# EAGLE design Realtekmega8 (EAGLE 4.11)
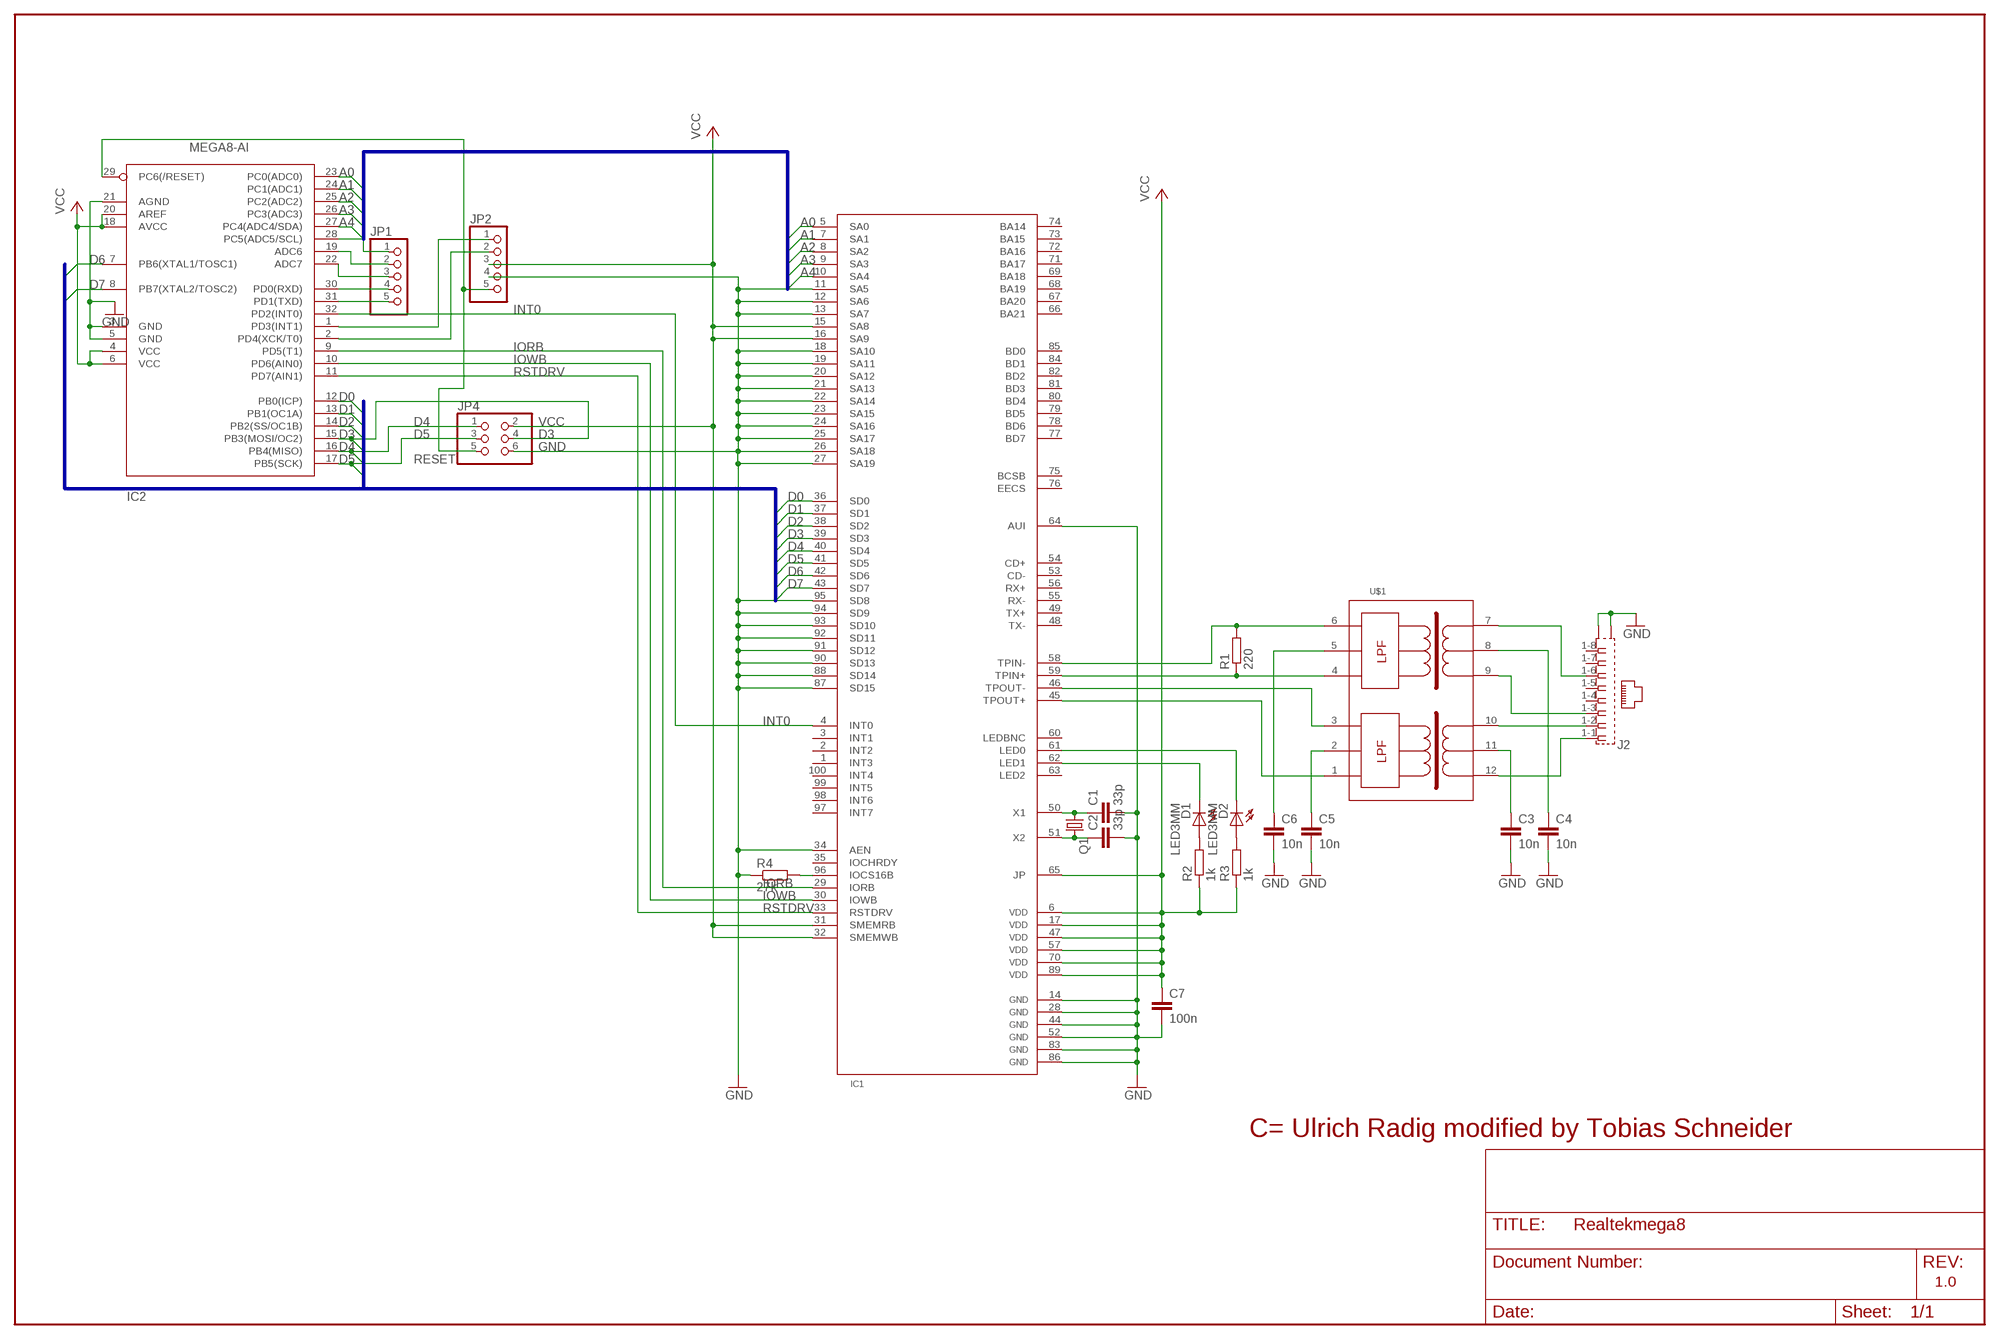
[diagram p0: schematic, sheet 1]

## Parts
C1  33p  C-EUC1206  [C1206]
C2  33p  C-EUC1206  [C1206]
C3  10n  C-EUC1206  [C1206]
C4  10n  C-EUC1206  [C1206]
C5  10n  C-EUC1206  [C1206]
C6  10n  C-EUC1206  [C1206]
C7  100n  C-EUC1206  [C1206]
D1  LED3MM  [LED3MM]
D2  LED3MM  [LED3MM]
IC1  RTL8019  [TQPF100]
IC2  MEGA8-AI  [TQFP32-08]
J2  557786-1  [557786-1]
JP1  PINHD-1X5  [1X05]
JP2  PINHD-1X5  [1X05]
JP4  PINHD-2X3  [2X03]
Q1  HC49U-H  [HC49U-H]
R1  220  R-EU_R1206  [R1206]
R2  1k  R-EU_M1206  [M1206]
R3  1k  R-EU_M1206  [M1206]
R4  27k  R-EU_M1206  [M1206]
U$1  20F001  [DIL16/12]

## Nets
A0: IC1.5(SA0) IC2.23(PC0(ADC0))
A1: IC1.7(SA1) IC2.24(PC1(ADC1))
A2: IC1.8(SA2) IC2.25(PC2(ADC2))
A3: IC1.9(SA3) IC2.26(PC3(ADC3))
A4: IC1.10(SA4) IC2.27(PC4(ADC4/SDA))
D0: IC1.36(SD0) IC2.12(PB0(ICP))
D1: IC1.37(SD1) IC2.13(PB1(OC1A))
D2: IC1.38(SD2) IC2.14(PB2(SS/OC1B))
D3: IC1.39(SD3) IC2.15(PB3(MOSI/OC2)) JP4.4
D4: IC1.40(SD4) IC2.16(PB4(MISO)) JP4.1
D5: IC1.41(SD5) IC2.17(PB5(SCK)) JP4.3
D6: IC1.42(SD6) IC2.7(PB6(XTAL1/TOSC1))
D7: IC1.43(SD7) IC2.8(PB7(XTAL2/TOSC2))
GND: C1.2 C2.2 C3.2 C4.2 C5.2 C6.2 C7.2 IC1.11(SA5) IC1.12(SA6) IC1.13(SA7) IC1.14(G1) IC1.18(SA10) IC1.19(SA11) IC1.20(SA12) IC1.21(SA13) IC1.22(SA14) IC1.23(SA15) IC1.24(SA16) IC1.25(SA17) IC1.26(SA18) IC1.27(SA19) IC1.28(G2) IC1.34(AEN) IC1.44(G3) IC1.52(G4) IC1.64(AUI) IC1.83(G5) IC1.86(G6) IC1.87(SD15) IC1.88(SD14) IC1.90(SD13) IC1.91(SD12) IC1.92(SD11) IC1.93(SD10) IC1.94(SD9) IC1.95(SD8) IC2.3(GND) IC2.5(GND) IC2.21(AGND) J2.G1(S2) J2.G2(S1) JP2.4 JP4.6 R4.1
INT0: IC1.4(INT0) IC2.32(PD2(INT0))
IORB: IC1.29(IORB) IC2.9(PD5(T1))
IOWB: IC1.30(IOWB) IC2.10(PD6(AIN0))
N$1: J2.1-1 U$1.12
N$2: J2.1-2 U$1.10
N$3: D2.K(C) IC1.61(LED0)
N$4: D1.K(C) IC1.62(LED1)
N$5: D1.A R2.2
N$6: J2.1-3 U$1.9
N$7: J2.1-6 U$1.7
N$8: IC1.58(TPIN-) R1.2 U$1.6
N$9: IC1.59(TPIN+) R1.1 U$1.4
N$10: IC1.46(TPOUT-) U$1.3
N$11: IC1.45(TPOUT+) U$1.1
N$12: C5.1 U$1.2
N$13: C6.1 U$1.5
N$14: C1.1 IC1.50(X1) Q1.1
N$15: C2.1 IC1.51(X2) Q1.2
N$16: C3.1 U$1.11
N$17: C4.1 U$1.8
N$18: D2.A R3.2
N$23: IC2.28(PC5(ADC5/SCL)) JP1.1
N$24: IC2.19(ADC6) JP1.2
N$25: IC2.22(ADC7) JP1.3
N$26: IC2.30(PD0(RXD)) JP1.4
N$27: IC2.31(PD1(TXD)) JP1.5
N$28: IC2.1(PD3(INT1)) JP2.1
N$29: IC2.2(PD4(XCK/T0)) JP2.2
N$31: IC1.96(IOCS16B) R4.2
RESET: IC2.29(PC6(/RESET)) JP2.5 JP4.5
RSTDRV: IC1.33(RSTDRV) IC2.11(PD7(AIN1))
VCC: C7.1 IC1.6(V1) IC1.15(SA8) IC1.16(SA9) IC1.17(V2) IC1.31(SMEMRB) IC1.32(SMEMWB) IC1.47(V3) IC1.57(V4) IC1.65(JP) IC1.70(V5) IC1.89(V6) IC2.4(VCC) IC2.6(VCC) IC2.18(AVCC) IC2.20(AREF) JP2.3 JP4.2 R2.1 R3.1
Unconnected: IC1.1(INT3) IC1.2(INT2) IC1.3(INT1) IC1.35(IOCHRDY) IC1.48(TX-) IC1.49(TX+) IC1.53(CD-) IC1.54(CD+) IC1.55(RX-) IC1.56(RX+) IC1.60(LEDBNC) IC1.63(LED2) IC1.66(BA21) IC1.67(BA20) IC1.68(BA19) IC1.69(BA18) IC1.71(BA17) IC1.72(BA16) IC1.73(BA15) IC1.74(BA14) IC1.75(BCSB) IC1.76(EECS) IC1.77(BD7) IC1.78(BD6) IC1.79(BD5) IC1.80(BD4) IC1.81(BD3) IC1.82(BD2) IC1.84(BD1) IC1.85(BD0) IC1.97(INT7) IC1.98(INT6) IC1.99(INT5) IC1.100(INT4) J2.1-4 J2.1-5 J2.1-7 J2.1-8

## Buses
D[0..7]
A[0..4]

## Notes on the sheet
- C= Ulrich Radig modified by Tobias Schneider
- 1.0

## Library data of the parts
C1-C7 = rcl:C-EU: CAPACITOR, European symbol
D1 D2 = led:LED3MM: LED
IC1 = Realtek:RTL8019
IC2 = avr:MEGA8: MICROCONTROLLER 8 Kbytes FLASH 1 kbytes SRAM 512 bytes EEPROM USART 6-channel 10 bit ADC 2-channel 8 bit ADC
J2 = con-amp:557786-1: AMP CONNECTOR
JP1 JP2 = pinhead:PINHD-1X5: PIN HEADER
JP4 = pinhead:PINHD-2X3: PIN HEADER
Q1 = crystal:HC49U-H: CRYSTAL
R1-R4 = rcl:R-EU_: RESISTOR, European symbol
U$1 = Realtek:20F001

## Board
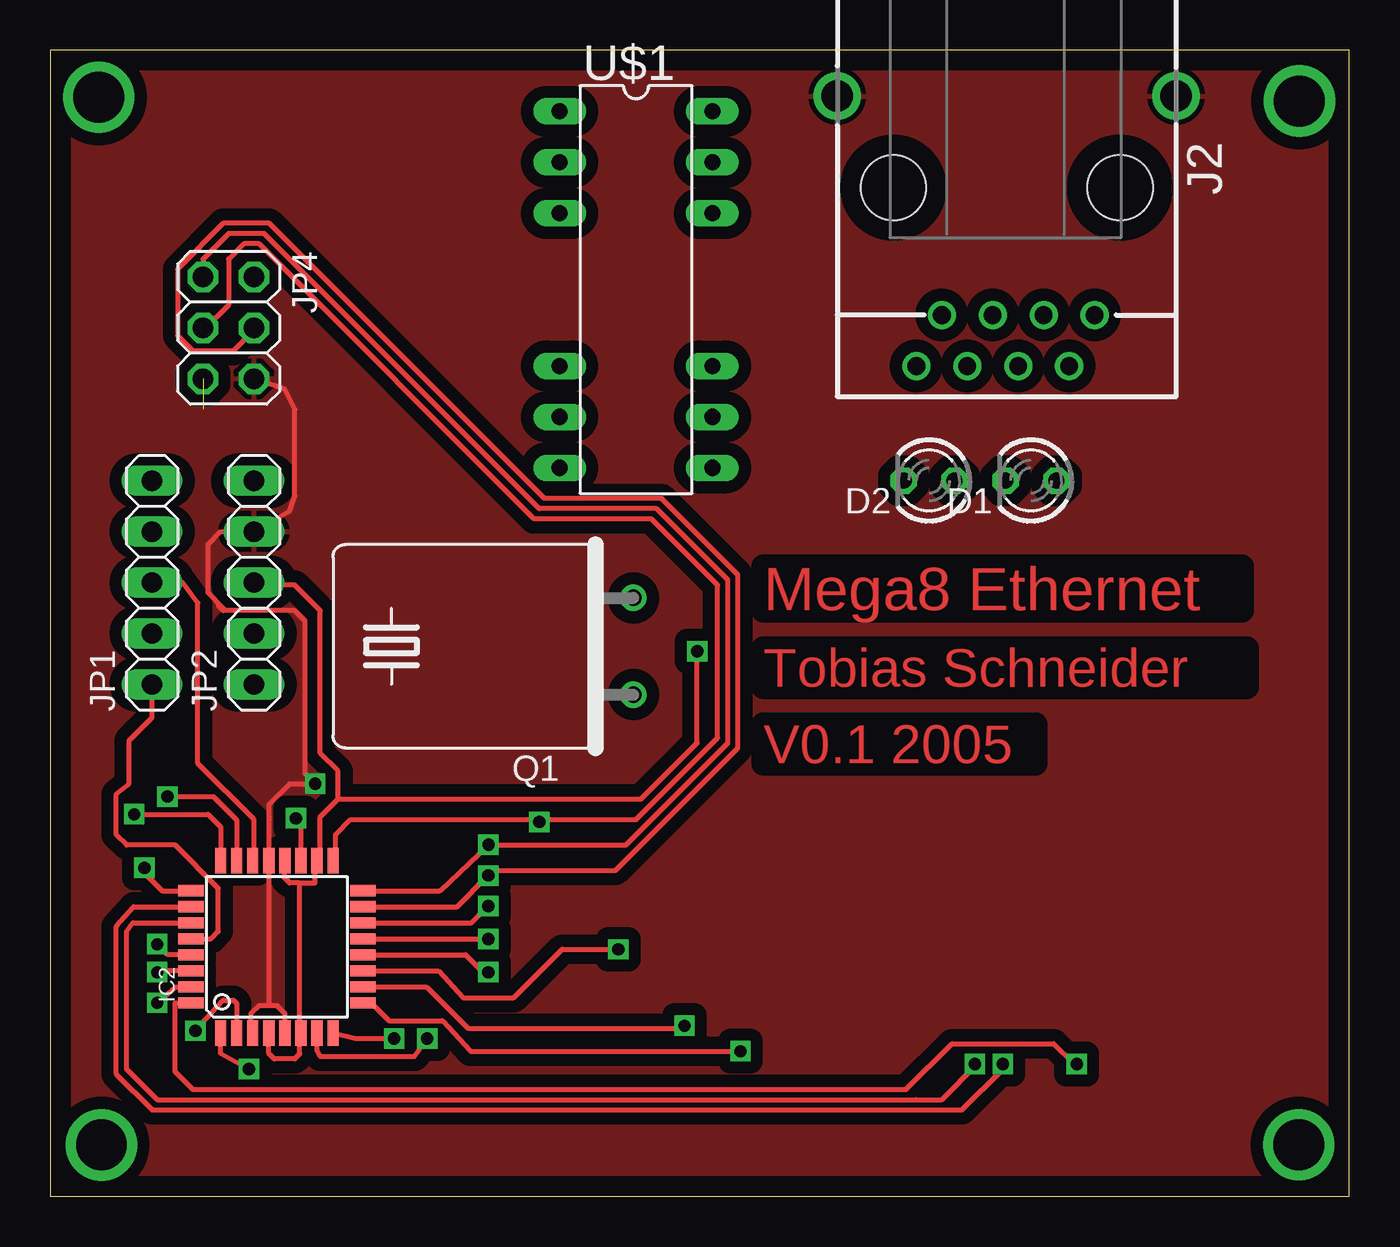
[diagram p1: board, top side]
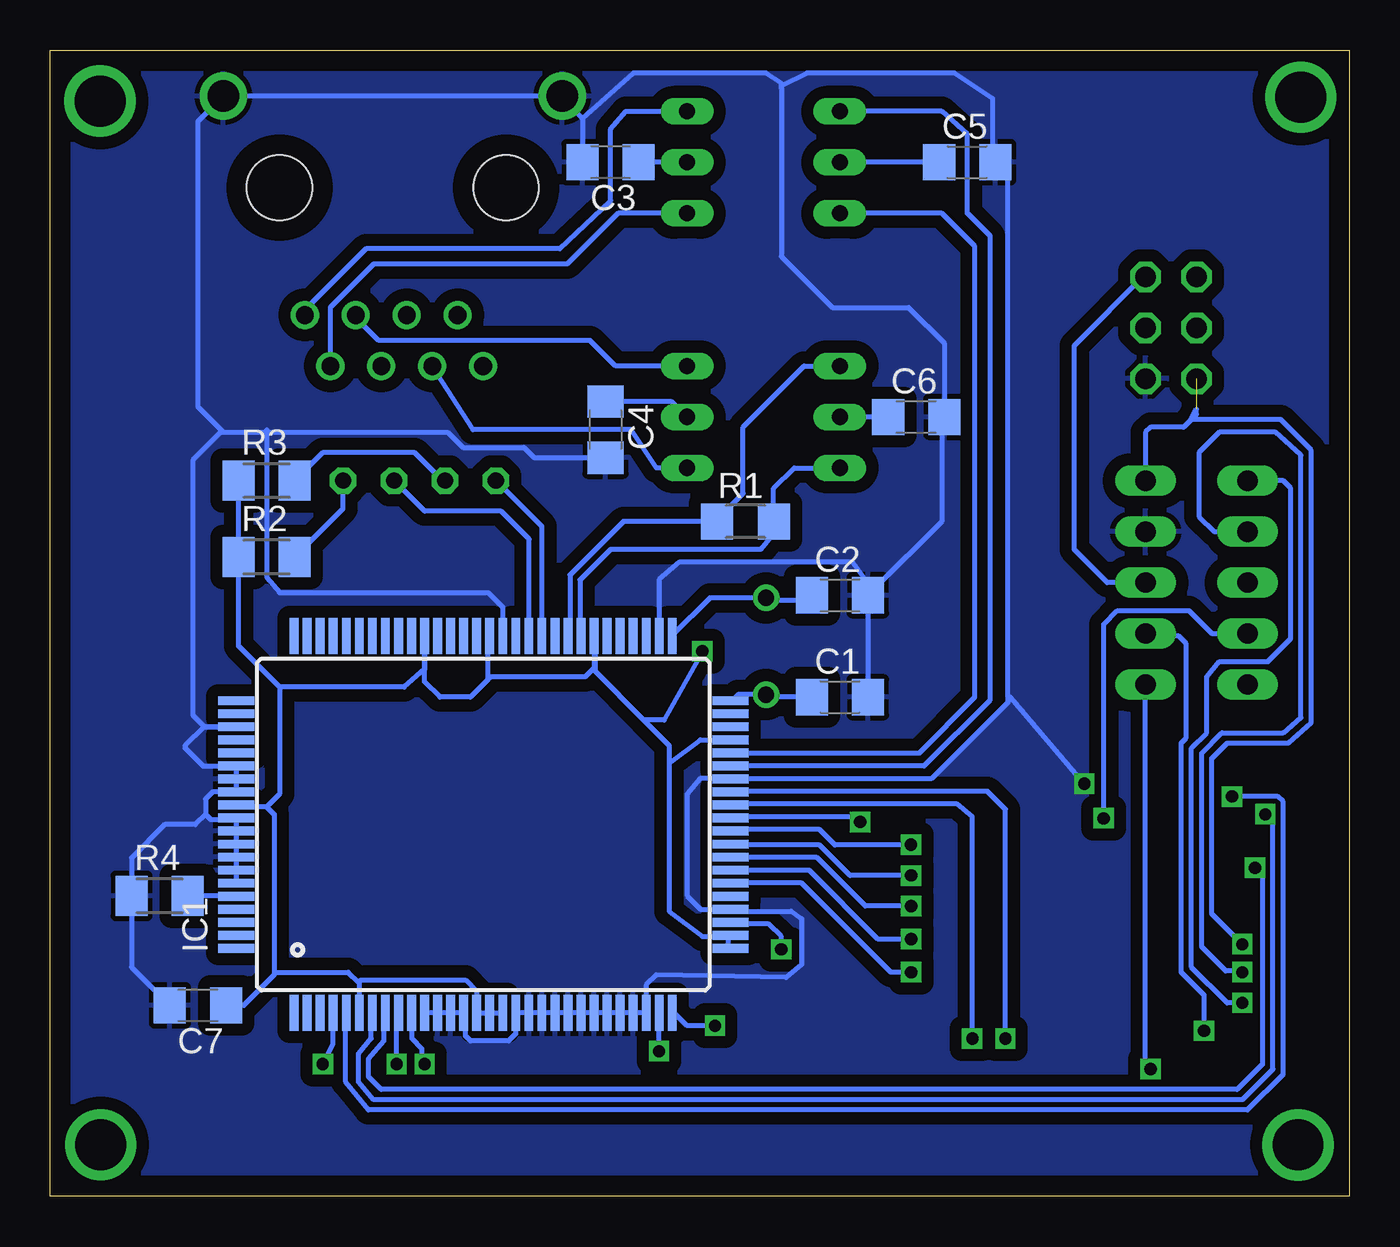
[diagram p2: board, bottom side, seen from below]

Size 64.77 x 57.15 mm. Coordinates in mm from the lower left corner, seen from the top.
Outline: 0,57.15 0,0 64.77,0 64.77,57.15 0,57.15
Copper layers (1*16): Top 0.035mm / dielectric 1.5mm / Bottom 0.035mm
Design rules "default": minimum track width 10mil, minimum drill 24mil, track to track 8mil, track to pad 8mil, pad to pad 8mil, via to via 8mil, smd to smd 8mil, copper to edge 40mil, drill to drill 8mil, minimum pad ring 10mil, minimum via ring 8mil, stop-mask expansion 4mil, vias tented up to drill 0mil, thermal gap 10mil

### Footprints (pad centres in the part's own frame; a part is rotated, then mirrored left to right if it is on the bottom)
C1206 = smd 1.6 x 1.8: 1 -1.4,0; 2 1.4,0
LED3MM = drill 0.813 octagon: A -1.27,0; K 1.27,0
TQPF100 = smd 1.8 x 0.44: 1 -9.395,9.425; 2 -9.395,8.775; 3 -9.395,8.125; 4 -9.395,7.475; 5 -9.395,6.825; 6 -9.395,6.175; 7 -9.395,5.525; 8 -9.395,4.875; 9 -9.395,4.225; 10 -9.395,3.575; 11 -9.395,2.925; 12 -9.395,2.275; 13 -9.395,1.625; 14 -9.395,0.975; 15 -9.395,0.325; 16 -9.395,-0.325; 17 -9.395,-0.975; 18 -9.395,-1.625; 19 -9.395,-2.275; 20 -9.395,-2.925; 21 -9.395,-3.575; 22 -9.395,-4.225; 23 -9.395,-4.875; 24 -9.395,-5.525; 25 -9.395,-6.175; 26 -9.395,-6.825; 27 -9.395,-7.475; 28 -9.395,-8.125; 29 -9.395,-8.775; 30 -9.395,-9.425; 51 9.395,-9.425; 52 9.395,-8.775; 53 9.395,-8.125; 54 9.395,-7.475; 55 9.395,-6.825; 56 9.395,-6.175; 57 9.395,-5.525; 58 9.395,-4.875; 59 9.395,-4.225; 60 9.395,-3.575; 61 9.395,-2.925; 62 9.395,-2.275; 63 9.395,-1.625; 64 9.395,-0.975; 65 9.395,-0.325; 66 9.395,0.325; 67 9.395,0.975; 68 9.395,1.625; 69 9.395,2.275; 70 9.395,2.925; 71 9.395,3.575; 72 9.395,4.225; 73 9.395,4.875; 74 9.395,5.525; 75 9.395,6.175; 76 9.395,6.825; 77 9.395,7.475; 78 9.395,8.125; 79 9.395,8.775; 80 9.395,9.425 | smd 0.44 x 1.8: 31 -6.175,-12.32; 32 -5.525,-12.32; 33 -4.875,-12.32; 34 -4.225,-12.32; 35 -3.575,-12.32; 36 -2.925,-12.32; 37 -2.275,-12.32; 38 -1.625,-12.32; 39 -0.975,-12.32; 40 -0.325,-12.32; 41 0.325,-12.32; 42 0.975,-12.32; 43 1.625,-12.32; 44 2.275,-12.32; 45 2.925,-12.32; 46 3.575,-12.32; 47 4.225,-12.32; 48 4.875,-12.32; 49 5.525,-12.32; 50 6.175,-12.32; 81 6.175,12.32; 82 5.525,12.32; 83 4.875,12.32; 84 4.225,12.32; 85 3.575,12.32; 86 2.925,12.32; 87 2.275,12.32; 88 1.625,12.32; 89 0.975,12.32; 90 0.325,12.32; 91 -0.325,12.32; 92 -0.975,12.32; 93 -1.625,12.32; 94 -2.275,12.32; 95 -2.925,12.32; 96 -3.575,12.32; 97 -4.225,12.32; 98 -4.875,12.32; 99 -5.525,12.32; 100 -6.175,12.32
TQFP32-08 = smd 1.27 x 0.559: 1 -4.293,2.8; 2 -4.293,2; 3 -4.293,1.2; 4 -4.293,0.4; 5 -4.293,-0.4; 6 -4.293,-1.2; 7 -4.293,-2; 8 -4.293,-2.8; 17 4.293,-2.8; 18 4.293,-2; 19 4.293,-1.2; 20 4.293,-0.4; 21 4.293,0.4; 22 4.293,1.2; 23 4.293,2; 24 4.293,2.8 | smd 0.559 x 1.27: 9 -2.8,-4.293; 10 -2,-4.293; 11 -1.2,-4.293; 12 -0.4,-4.293; 13 0.4,-4.293; 14 1.2,-4.293; 15 2,-4.293; 16 2.8,-4.293; 25 2.8,4.293; 26 2,4.293; 27 1.2,4.293; 28 0.4,4.293; 29 -0.4,4.293; 30 -1.2,4.293; 31 -2,4.293; 32 -2.8,4.293
557786-1 = drill 0.889 round: 1-1 -4.445,6.35; 1-2 -3.175,8.89; 1-3 -1.905,6.35; 1-4 -0.635,8.89; 1-5 0.635,6.35; 1-6 1.905,8.89; 1-7 3.175,6.35; 1-8 4.445,8.89 | drill 1.575 pad 2.184 round: G1 -8.509,-4.572; G2 8.382,-4.572 | hole 3.251: -5.715,0; 5.588,0
1X05 = drill 1.016 long: 1 -5.08,0; 2 -2.54,0; 3 0,0; 4 2.54,0; 5 5.08,0
2X03 = drill 1.016 octagon: 1 -2.54,-1.27; 2 -2.54,1.27; 3 0,-1.27; 4 0,1.27; 5 2.54,-1.27; 6 2.54,1.27
HC49U-H = drill 0.813 round: 1 -2.413,-5.08; 2 2.413,-5.08
R1206 = smd 1.6 x 1.803: 1 -1.422,0; 2 1.422,0
M1206 = smd 1.6 x 2: 1 -1.4,0; 2 1.4,0
DIL16/12 = drill 0.813 long: 1 -8.89,-3.81; 2 -6.35,-3.81; 3 -3.81,-3.81; 4 3.81,-3.81; 5 6.35,-3.81; 6 8.89,-3.81; 7 8.89,3.81; 8 6.35,3.81; 9 3.81,3.81; 10 -3.81,3.81; 11 -6.35,3.81; 12 -8.89,3.81

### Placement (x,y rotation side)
C1  25.4,24.89 0 bottom
C2  25.4,29.97 0 bottom
C3  36.83,51.56 180 bottom
C4  37.08,38.23 270 bottom
C5  19.05,51.56 0 bottom
C6  21.59,38.86 0 bottom
C7  57.4,9.53 180 bottom
D1  48.9,35.69 180 top
D2  43.81,35.69 180 top
IC1  43.18,18.54 90 bottom
IC2  11.3,12.45 90 top
J2  47.62,50.29 180 top
JP1  5.08,30.61 90 top
JP2  10.16,30.61 90 top
JP4  8.89,43.31 270 top
Q1  24,27.43 90 top
R1  30.1,33.66 0 bottom
R2  53.98,31.88 0 bottom
R3  53.98,35.69 0 bottom
R4  59.31,14.99 0 bottom
U$1  29.21,45.21 270 top

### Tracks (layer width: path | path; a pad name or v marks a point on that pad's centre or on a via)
A0  (via drill 0.61)
  Top 0.254: 9.4,16.83 IC2.23 9.3,18.76 8.13,19.94 v5.84,19.94
  Bottom 0.254: 50.04,9.24 IC1.5 50.01,9.05 50.04,9.02 50.04,5.71 48.9,4.32 5.08,4.32 3.3,6.1 3.3,19.68 3.56,19.94 v5.84,19.94
A1  (via drill 0.61)
  Top 0.254: IC2.24 8.5,18.42 7.87,19.05 v4.19,19.05
  Bottom 0.254: IC1.7 48.77,9.08 48.77,7.87 49.4,7.11 49.4,5.71 48.64,4.83 5.33,4.83 3.81,6.35 3.81,18.67 v4.19,19.05
A2  (via drill 0.61)
  Top 0.254: v4.7,16.38 4.57,16.26 5.58,15.25 IC2.25
  Bottom 0.254: v4.7,16.38 4.32,16.38 4.32,6.6 5.59,5.33 48.26,5.33 48.9,5.97 48.9,6.86 48.13,7.75 48.13,8.89 48.01,9.02 48.05,9.07 IC1.8
A3  (via drill 0.61)
  Top 0.254: IC2.26 4.16,14.45 3.3,13.46 3.3,6.1 5.08,4.32 43.31,4.32
  Top 0.255: v47.5,6.6 47.5,6.35 45.47,4.32 43.31,4.32
  Bottom 0.254: 47.41,9.24 47.37,9.27 | 47.41,9.24 IC1.9 | 47.41,9.24 47.5,9.14 v47.5,6.6
A4  (via drill 0.61)
  Top 0.254: IC2.27 4.12,13.65 3.81,13.21 3.81,6.35 5.33,4.83 43.18,4.83
  Top 0.255: 43.18,4.83 44.45,4.83 46.23,6.6 v46.1,6.6
  Bottom 0.254: IC1.10 46.74,9.15 46.74,9.14 46.74,7.87 46.23,7.37 46.23,6.73 v46.1,6.6
D0  (via drill 0.61)
  Top 0.255: v21.84,11.18 21.59,11.18 20.72,12.05 IC2.12
  Bottom 0.254: IC1.36 27.3,15.62
  Bottom 0.255: 27.3,15.62 22.86,11.18 v21.84,11.18
D1  (via drill 0.61)
  Top 0.254: IC2.13 21.82,12.85 v21.84,12.83
  Bottom 0.254: v21.84,12.83 23.5,12.83 26.92,16.26 30.86,16.26 IC1.37
D2  (via drill 0.61)
  Top 0.254: IC2.14 21.01,13.65 v21.84,14.48
  Bottom 0.254: v21.84,14.48 24.13,14.48 26.54,16.89 30.86,16.89 | 30.86,16.89 IC1.38 | 30.86,16.89 31.11,16.89
D3  (via drill 0.61)
  Top 0.254: IC2.15 20.29,14.45 v21.84,16 22.1,16.26 28.19,16.26 34.29,22.35 34.29,30.99 30.48,34.8 24.64,34.8 10.92,48.51 8.64,48.51 6.35,46.23 6.35,42.93 7.11,42.16 9.14,42.16 10.16,43.18 JP4.4
  Bottom 0.254: IC1.39 30.65,17.57 30.48,17.53
  Bottom 0.255: 30.48,17.53 26.42,17.53 24.89,16 v21.84,16
D4  (via drill 0.61)
  Top 0.254: IC2.16 19.44,15.25 v21.85,17.53 28.7,17.53 33.78,22.61 33.78,30.73 30.23,34.29 24.38,34.29 10.67,48.01 8.89,48.01 7.62,46.74 JP4.1 7.62,45.72
  Bottom 0.254: 31.11,18.29 31.04,18.22 IC1.40
  Bottom 0.255: 31.11,18.29 26.42,18.29 25.65,17.53 v21.84,17.53 v21.85,17.53
D5  (via drill 0.61)
  Top 0.254: IC2.17 14.22,17.14 14.22,18.03 14.99,18.8 15.88,18.8 | v24.38,18.67 24.64,18.8 29.21,18.8 33.27,22.86 33.27,30.48 29.97,33.78 24.13,33.78 10.41,47.5 9.65,47.5 8.89,46.74 8.89,44.45 7.62,43.18 JP4.3
  Top 0.255: v24.38,18.67 24.38,18.8 15.88,18.8
  Bottom 0.254: 30.73,18.92 30.79,18.87 IC1.41 30.8,18.87 30.73,18.8 30.61,18.92
  Bottom 0.255: v24.38,18.67 24.38,18.54 24.77,18.92 30.61,18.92
D6  (via drill 0.61)
  Top 0.254: IC2.7 13.3,7.27 13.46,6.99 18.16,6.99 v18.8,7.87
  Bottom 0.254: v18.8,7.87 18.8,18.92 19.56,19.56 30.61,19.56 30.86,19.43 | 30.86,19.43 | 30.86,19.43 IC1.42
D7  (via drill 0.61)
  Top 0.254: IC2.8 15.24,7.87 v17.14,7.87
  Bottom 0.254: v17.14,7.87 17.14,19.3 18.03,20.19 30.86,20.19 30.89,20.17 | 30.89,20.17 30.99,20.19 | 30.89,20.17 IC1.43
GND  (via drill 0.61)
  Top 0.254: IC2.3 10.1,8.07 10.03,8 10.03,9.14 10.41,9.53 10.92,9.53 | 10.92,16.76 IC2.21 | 10.92,16.76 10.92,18.8 | 10.92,18.8 10.92,18.92 | JP4.6 11.68,40.26 12.19,39.24 12.19,34.92 11.94,34.16 JP2.4 8.51,33.15 7.87,32.51 7.87,30.1 8.64,29.34 8.51,29.34 | v13.21,20.57 13.46,20.95 | v13.21,20.57 11.94,20.57 10.92,19.56 10.92,18.8 | v13.21,20.57 12.7,21.08 12.7,28.7 12.19,29.21 8.64,29.21 8.51,29.34 | 8.51,29.34 8.38,29.46 | 10.92,16.76 10.92,9.65 10.92,9.53 | IC2.5 11.7,9.12 11.3,9.53 10.92,9.53
  Bottom 0.254: 38.23,53.72 C3.2 | 38.23,53.72 39.37,54.86 J2.G2 J2.G1 | J2.G1 56.26,54.86 | 56.2,38.16 57.4,39.37 57.4,53.59 J2.G1 | 56.2,38.16 56.13,38.1 | 34.41,27.82 34.42,27.81 | 34.41,27.82 IC1.52 | C6.2 20.19,42.54 21.97,44.32 25.78,44.32 28.32,46.86 28.32,55.24 | 23.88,30.1 C2.2 | 23.88,30.1 23.75,30.22 24.77,31.62 33.4,31.62 34.41,30.75 34.41,27.82 | 23.88,30.1 24,30.23 C1.2 | 28.32,55.24 28.32,55.37 27.05,56.01 19.68,56.01 17.78,54.74 17.78,51.44 17.65,51.31 17.65,51.44 | 17.65,51.44 C5.2 | 38.23,53.72 38.22,53.72 35.69,56.01 29.08,56.01 28.32,55.5 28.32,55.24 | C4.2 40.64,36.83 41.15,37.34 44.2,37.34 44.96,38.1 53.98,38.1 | 56.2,38.16 56.26,38.1 | 56.26,38.1 53.98,38.1 | IC1.64 42.2,29.38 42.93,30.1 53.34,30.1 53.98,30.86 53.98,38.1 | 53.98,38.1 53.98,38.23 | 56.26,38.1 57.66,36.7 57.66,24 57.07,23.42 IC1.83 57.1,23.42 58.04,22.48 58.04,22.35 57.15,21.46 IC1.86 IC1.87 | IC1.87 55.5,20.7 | IC1.87 55.5,20.19 | 55.5,20.19 IC1.88 56.67,20.17 57.02,19.81 57.02,19.05 | 55.5,20.19 | 57.02,19.05 56.77,18.8 55.37,18.8 55.5,18.8 IC1.90 IC1.91 | IC1.91 55.5,18.16 | IC1.91 IC1.92 | IC1.92 55.5,17.53 | IC1.92 IC1.93 | IC1.93 55.5,16.89 | IC1.93 IC1.94 | IC1.94 55.5,16.26 | IC1.95 IC1.94 | 60.71,15.11 60.71,16.89 59.05,18.54 57.53,18.54 57.02,19.05 | 60.71,15.11 R4.1 | 60.71,15.11 60.71,11.43 C7.2 | 17.65,51.44 17.53,51.44 17.02,50.93 17.02,24.89 | 17.02,24.89 17.02,24.64 20.84,20.82 IC1.44 32.38,20.83 33.02,20.07 33.02,14.99 32.35,14.32 IC1.34 30.51,14.32 30.48,14.35 30.35,14.22 27.81,14.22 27.3,13.84 27.3,11.56 28.07,10.92 34.54,11.05 35.05,10.54 IC1.28 35.68,9.15 35.69,9.14 IC1.27 IC1.26 | 39.6,9.25 39.62,9.27
  Bottom 0.254: 39.6,9.25 IC1.21 40.13,9.15 40.26,9.27 | 39.6,9.25 39.5,9.15 IC1.22 38.48,9.15 38.35,9.27 38.3,9.22 IC1.23 37.72,9.15 37.72,9.14 37.72,9.15 | 40.26,9.27 | 40.26,9.27 IC1.20 40.89,9.15 40.89,9.14 40.9,9.15 IC1.19 41.53,9.15 41.53,9.14 41.53,9.15 IC1.18 41.55,8.1 41.91,7.75 43.81,7.75 44.07,8 44.07,9.14 44.07,9.15 IC1.14 | 44.2,9.14 44.19,9.15 IC1.14 | 44.95,9.15 IC1.13 | IC1.14 44.95,9.15 | 44.95,9.15 44.96,9.14 | 44.95,9.15 IC1.12 | IC1.12 45.46,9.15 45.47,9.14 | IC1.11 IC1.12 | IC1.26 36.45,9.15 36.45,9.14 | IC1.26 36.95,9.15 36.96,9.14 36.96,9.15 IC1.25 37.72,9.15 | 37.72,9.15 IC1.24 | 17.02,24.89 16.89,24.89 v13.21,20.57
  Bottom 0.255: C6.2 20.32,38.86 20.32,33.65 23.75,30.22
  pour Bottom (isolate 0.61): -1.27,59.18 -1.27,-2.16 66.04,-2.16 66.04,59.31
  pour Top (isolate 0.61): -0.76,58.17 -0.76,-0.76 66.04,-0.76 66.04,58.17 65.79,58.17
INT0  (via drill 0.61)
  Top 0.254: 41.53,5.33 7.11,5.33 6.22,6.22 6.22,9.65 IC2.32
  Top 0.255: 41.53,5.33 42.67,5.33 44.96,7.62 50.04,7.62 51.05,6.6 v51.18,6.6
  Bottom 0.254: IC1.4 50.67,9.13 50.67,7.62 v51.18,6.6
IORB  (via drill 0.61)
  Top 0.254: IC2.9 16.01,9.65 16.89,8.76 19.56,8.76 20.95,7.24 v34.42,7.24
  Bottom 0.254: IC1.29 v34.42,7.24
IOWB  (via drill 0.61)
  Top 0.254: IC2.10 17.37,10.45
  Top 0.255: 17.37,10.45 18.76,10.45 20.83,8.38 31.75,8.38 v31.62,8.51 31.5,8.64
  Bottom 0.254: IC1.30 33.66,9.15 33.02,8.51 v31.62,8.51
N$1
  Bottom 0.254: U$1.12 36.07,54.1 36.83,53.21 36.83,49.66 39.37,47.24 49.02,47.24 52.2,44.07 J2.1-1
N$2
  Bottom 0.254: U$1.10 36.45,49.02 38.99,46.48 48.64,46.48 50.8,44.32 J2.1-2 50.8,41.27
N$3
  Bottom 0.254: IC1.61 40.26,33.4 D2.K
N$4
  Bottom 0.254: D1.K 46.1,34.16 42.29,34.16 40.89,32.77 40.89,27.93 | 40.89,27.93 40.89,27.81 | IC1.62 40.89,27.93
N$5
  Bottom 0.254: R2.2 50.16,34.29 D1.A
N$6
  Bottom 0.254: U$1.9 36.58,41.4 37.85,42.67 48.39,42.67 49.53,43.81 J2.1-3
N$7
  Bottom 0.254: U$1.7 34.54,36.32 35.81,38.23 43.69,38.23 J2.1-6
N$8
  Bottom 0.254: U$1.6 27.69,36.32 28.7,35.31 28.7,33.78 28.57,33.66 R1.2 28.68,33.05 29.34,32.26 36.83,32.26 38.35,30.73 38.35,27.81 38.3,27.86 IC1.58
N$9
  Bottom 0.254: U$1.4 27.18,41.4 30.23,38.35 30.23,35.05 31.62,33.66 R1.1 36.2,33.66 38.86,30.99 38.86,28.07 38.95,27.97 IC1.59
N$10
  Bottom 0.254: U$1.3 20.32,49.02 18.67,47.37 18.67,24.89 21.46,22.1 30.86,22.1 30.88,22.12 | 30.88,22.12 30.99,22.1 | 30.88,22.12 IC1.46
N$11
  Bottom 0.254: U$1.1 20.32,54.1 19.05,52.96 19.05,49.02 17.91,47.88 17.91,24.77 21.21,21.46 IC1.45 | IC1.45 30.99,21.46 | IC1.45
N$12
  Bottom 0.254: C5.1 U$1.2
N$13
  Bottom 0.254: 22.86,38.86 C6.1 U$1.5
N$14
  Bottom 0.254: 30.86,24.64 | 30.86,24.64 IC1.50 | 30.86,24.64 30.48,25.02 Q1.1 29.21,24.89 C1.1
N$15
  Bottom 0.254: IC1.51 33.78,27.94 31.88,29.84 Q1.2 29.08,29.72 26.67,29.72 26.67,29.84 C2.1
N$16
  Bottom 0.254: 35.69,51.56 C3.1 U$1.11
N$17
  Bottom 0.254: C4.1 33.78,39.63 U$1.8
N$18
  Bottom 0.254: R3.2 51.18,37.08 46.61,37.08 45.34,35.81 45.09,35.81 D2.A
N$19  (via drill 2.54)
  other vias: 2.42,54.81
N$20  (via drill 2.54)
  other vias: 2.56,2.57
N$21  (via drill 2.54)
  other vias: 62.25,2.58
N$22  (via drill 2.54)
  other vias: 62.28,54.61
N$23
  Top 0.254: IC2.28 8.02,12.85 8.38,13.21 8.38,15.37 6.22,17.53 3.81,17.53 3.3,18.03 3.3,20.07 3.94,20.57 3.94,22.73 5.08,23.88 JP1.1
N$24  (via drill 0.61)
  Top 0.254: v12.25,18.85 12.19,18.8 12.5,18.48 IC2.19
  Bottom 0.254: v12.25,18.85 12.25,28.52 11.56,29.21 8,29.21 6.86,28.07 JP1.2
N$25
  Top 0.254: IC2.22 10.16,17.14 10.16,18.8 7.37,21.59 7.37,29.59 6.6,30.61 JP1.3
N$26  (via drill 0.61)
  Top 0.254: IC2.30 5.4,11.25 v5.33,11.18
  Bottom 0.254: 3.3,23.11 2.41,23.88 2.41,36.96 3.68,38.1 6.48,38.1 7.49,37.08 7.49,33.91 6.73,33.15 JP1.4 | v5.33,11.18 5.4,11.25
  Bottom 0.255: 5.4,11.25 6.17,11.25 7.37,12.45 7.37,22.1 6.35,23.11 3.3,23.11
N$27  (via drill 0.61)
  Top 0.254: IC2.31 6.25,10.45 v5.33,9.65
  Bottom 0.254: 7.11,24.38 7.11,25.91 6.48,26.67 4.06,26.67 2.92,27.81 2.92,35.31 3.3,35.69 JP1.5
  Bottom 0.255: v5.33,9.65 6.1,9.65 7.87,11.43 7.87,22.35 7.11,23.11 7.11,24.38
N$28  (via drill 0.61)
  Top 0.254: IC2.1 8.5,7.12 v9.91,6.35
  Bottom 0.255: v9.91,6.35 9.91,6.1 10.16,6.35 JP2.1
N$29  (via drill 0.61)
  Top 0.254: IC2.2 9.3,9.62 9.14,9.78 8.64,9.78 v7.24,8.26
  Bottom 0.254: 8.13,24.26 8.13,22.86 8.13,27.56 8.51,27.94 10.29,27.94 JP2.2
  Bottom 0.255: v7.24,8.26 7.24,10.03 8.38,11.18 8.38,22.61 8.13,22.86
N$31
  Bottom 0.254: IC1.96 55.5,14.98 55.5,14.99 R4.2
RESET  (via drill 0.61)  (1 unrouted)
  Top 0.254: IC2.29 5.86,12.05 v5.33,12.57
  Bottom 0.254: 7.87,38.73 7.62,38.99 7.62,39.24 7.87,38.73 | 7.87,38.73 8.26,38.35 9.91,38.35 10.16,38.1 10.16,35.56 | 10.16,35.56 JP2.5 | 10.16,35.56 10.29,35.43 | 3.05,22.61 1.91,23.62 1.91,37.21 3.43,38.73 7.87,38.73
  Bottom 0.255: v5.33,12.57 6.86,14.1 6.86,21.84 6.1,22.61 3.05,22.61
RSTDRV  (via drill 0.61)
  Top 0.254: IC2.11 19.36,11.25 20.57,9.91 23.11,9.91 25.53,12.32 v28.32,12.32
  Bottom 0.254: v28.32,12.32 28.32,12.95 28.96,13.59 30.73,13.59 30.81,13.67 IC1.33
VCC  (via drill 0.61)
  Top 0.254: IC2.4 10.9,7.13 11.18,6.86 12.19,6.86 12.45,7.11 12.45,8 12.5,8.06 IC2.6 12.45,8.76 12.45,15.62 | 12.45,15.62 13.21,15.62 13.21,16.13 IC2.18 13.46,17.14 13.46,18.92 14.35,19.81 | 12.45,15.62 11.94,15.62 11.68,15.88 11.68,16.13 IC2.20 | 10.16,30.48 JP2.3 | 14.35,19.81 29.46,19.81 32.26,22.61 v32.26,27.18 | 14.35,19.81 14.35,21.21 13.46,22.1 13.46,29.21 12.19,30.48 10.16,30.48 | 10.16,30.48 10.16,30.73
  Bottom 0.254: R3.1 55.38,35.56 55.37,35.56 55.38,35.56 R2.1 55.38,27.43 53.34,25.4 | 46.1,27.81 IC1.70 46.1,25.66 45.34,24.89 43.81,24.89 42.93,25.78 | 46.1,27.81 46.1,27.69 | 53.34,25.4 53.34,20.07 53.98,19.43 | IC1.89 55.54,19.52 55.63,19.43 53.98,19.43 | 53.34,25.4 47.12,25.4 46.1,26.29 46.1,27.81 | 46.1,27.81 IC1.70 | 42.8,27.94 | 42.8,27.94 IC1.65 | 42.93,25.78 42.93,27.81 42.8,27.94 | C7.1 55.12,9.53 53.59,11.05 53.59,11.18 | 53.59,11.18 53.59,19.05 53.98,19.43 | IC1.6 49.35,10.62 49.4,10.67 | 49.4,10.67 49.91,11.18 53.59,11.18 | IC1.47 32.35,22.77 33.91,21.59 | 33.91,21.59 33.91,14.22 32.26,12.95 30.99,12.95 | 30.99,12.95 30.93,13.02 IC1.32 | IC1.16 42.8,9.15 42.8,9.14 | IC1.16 IC1.15 43.51,10.23 44.07,10.79 49.28,10.79 49.4,10.67 | 42.17,9.15 IC1.17 | IC1.16 42.17,9.15 | 42.17,9.15 42.16,9.14 | IC1.31 30.94,12.37 30.99,12.32 30.99,12.95 | 33.91,21.59 33.91,22.48 35.18,23.75 | 35.18,23.75 37.59,26.16 37.59,27.81 37.72,27.94 | 37.72,27.94 | 37.72,27.94 IC1.57 37.66,26.35 38.1,25.91 42.8,25.91 42.93,25.78 | JP2.3 12.06,30.61 13.72,32.26 13.72,42.42 10.16,45.97 JP4.2 | 35.18,23.75 34.16,23.75 v32.26,27.18

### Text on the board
Top: Mega8 Ethernet | Tobias Schneider | V0.1 2005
